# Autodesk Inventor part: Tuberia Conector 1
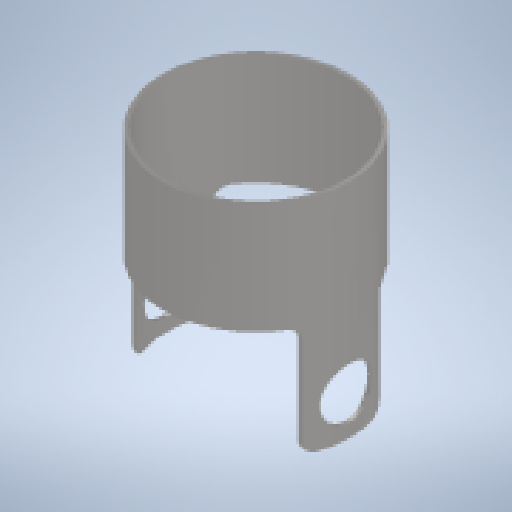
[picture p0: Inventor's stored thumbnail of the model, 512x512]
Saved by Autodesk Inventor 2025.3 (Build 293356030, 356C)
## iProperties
Created: 2025-10
Part Number: Tuberia Conector 1
Material: Hierro, fundido
Document SubType Name: Modeling
Designer: Asus
Density: 7.15 g/cm^3
Appearance: Inoxidable - Bruñido
Author: Asus
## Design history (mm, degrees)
sketch "Boceto1"
  geometry: C1 r 84.138 at (0, 0); C2 r 80.738 at (0, 0); 1 further point
  constraints: 2 centre point, 2 coincident
  dimensions: "d0" = 168.275 diameter of C1; "d1" = 3.4 radial gap between concentric circles of C1 C2
extrude "Extrusión1" new body sketch "Boceto1" distance "d2" = 200; taper "d3" = 0 deg
sketch "Boceto2"
  geometry: L1 (-200, -80.738)-(-200, 80.738) reference; L2 (-200, 84.138)-(-200, -84.138) reference; L3 (-100, 84.138)-(-100, 35); L4 (-100, 35)-(-200, 35); L5 (-200, -35)-(-100, -35); L6 (-100, -35)-(-100, -84.138); L7 (0, 84.138)-(-200, 84.138) reference; L8 (0, -84.138)-(-200, -84.138) reference; L9 (-240, 0)-(40, 0) reference; L10 (-100, 84.138)-(-200, 84.138); L11 (-200, 84.138)-(-200, 35); L12 (-200, 35)-(-100, 35); L13 (-100, 35)-(-100, 84.138); L14 (-200, -35)-(-100, -35); L15 (-100, -35)-(-100, -84.138); L16 (-100, -84.138)-(-200, -84.138); L17 (-200, -84.138)-(-200, -35); 3 further points
  constraints: 24 end point, 4 parallel, 3 perpendicular, 3 point on line, 2 horizontal, 2 midpoint, 1 vertical
  dimensions: "d4" = 70 distance between parallel lines of L5 L4; "d5" = 35 distance between parallel lines of L9 L4 (= 0.5 x d4); "d6" = 100 distance between parallel lines of L1 L6
extrude "Extrusión2" cut sketch "Boceto2" extent not by distance; stored distance "d7" = 0; taper "d8" = 0 deg
sketch "Boceto3"
  geometry: L1 (-240, 0)-(40, 0) reference; L2 (-200, -35)-(-200, 35) reference; 2 further points
  dimensions: "d9" = 0 distance from line of L1 point (-165, 0); "d10" = 35 distance from line of point (-165, 0) L2
hole "Agujero1" sketch "Boceto3" at (-165, 0) diameter "d11" = 46; stored, may be unused: countersink angle "d15" = 90 deg, drill point angle "d17" = 118 deg; dims "d12" = 6, "d13" = 4, "d14" = 2, "d16" = 8
fillet "Empalme1" dims "d18" = 10
node "Sólido1"
